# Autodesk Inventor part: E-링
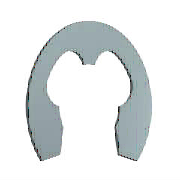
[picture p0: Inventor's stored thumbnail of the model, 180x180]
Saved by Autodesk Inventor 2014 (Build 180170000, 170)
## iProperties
IsCustomPart: 1
Created: 2012-02
Part Number: E-링
Material: 강철, 연강
Description: 일반용 테이퍼 및 줄어든 횡단면 리테이닝 링 - E-링 외부 시리즈 3CM1 리테이닝 링
Document SubType Name: Modeling
Standard: ANSI B27.7
Designer: mduedu
Standard Revision: 1999
Standards Organization: ANSI
Language: ko-KR
Size Designation: 6
Categories: <MemberInstance><Categories><Category DisplayName="샤프트 부품" InternalName="7f7aeb1f-a693-4053-b835-cee3144e0d98" Mnemonic="SHFT"><Category DisplayName="써클립" Inter
Density: 1 g/cm^3
Appearance: 파란색 - 벽 페인트 - 광택
Author: mduedu
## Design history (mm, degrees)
sketch "스케치1"
  geometry: L1 (-0.485, 0.024)-(0, 0.024) reference; L2 (-3.206, 0)-(3.486, 0) reference; L3 (-2.223, -3.946)-(2.223, -3.946); L4 (0, 1.949)-(0, -3.479) reference; L5 (-2.91, -2.006)-(-2.435, -2.006); L6 (-0.485, -0.066)-(-0.485, 0.405); L7 (0, 2.574)-(2.53, 2.574); L8 (-2.223, -3.946)-(-3.022, -6.291); L9 (0, -0.551)-(-1.278, -0.551); L10 (2.223, -3.946)-(3.022, -6.291); L11 (2.91, -2.006)-(2.435, -2.006); L12 (0.485, -0.066)-(0.485, 0.405); C1 r 3 at (0, -2.976); A1 r 2.425 centre (0, -2.976) between (-2.297, -2.199) and (-2.223, -3.946); A2 r 0.485 centre (0, -0.066) between (-0.485, -0.066) and (0.485, -0.066); A3 r 5.55 centre (0, -2.976) between (4.27, -6.521) and (-4.27, -6.521); A4 r 3.88 centre (0, -2.976) between (-0.97, 0.78) and (-3.424, -1.15); A5 r 0.388 centre (-0.873, 0.405) between (-0.485, 0.405) and (-0.97, 0.78); A6 r 0.582 centre (-2.91, -1.424) between (-3.424, -1.15) and (-2.91, -2.006); A7 r 0.145 centre (-2.435, -2.152) between (-2.297, -2.199) and (-2.435, -2.006); A8 r 0.727 centre (-3.711, -6.057) between (-4.27, -6.521) and (-3.022, -6.291); A9 r 0.727 centre (3.711, -6.057) between (3.022, -6.291) and (4.27, -6.521); A10 r 2.425 centre (0, -2.976) between (2.223, -3.946) and (2.297, -2.199); A11 r 0.145 centre (2.435, -2.152) between (2.435, -2.006) and (2.297, -2.199); A12 r 0.582 centre (2.91, -1.424) between (2.91, -2.006) and (3.424, -1.15); A13 r 3.88 centre (0, -2.976) between (3.424, -1.15) and (0.97, 0.78); A14 r 0.388 centre (0.873, 0.405) between (0.97, 0.78) and (0.485, 0.405); 1 further point
  constraints: 30 point on circle, 20 end point, 15 centre point, 13 symmetric about line, 12 tangent, 8 point on line, 4 parallel, 2 coincident, 2 horizontal, 1 concentric, 1 perpendicular, 1 vertical alignment, 9 other
  dimensions: "d0" = 6 diameter of C1 (= WD); "d3" = 0.97 distance from line of A1.centre L3 (= 0.2 x ND); "d4" = 0.485 radius of A2 (= 0.1 x ND); "d5" = 11.1 diameter of A3 (= SD2); "d8" = 3.88 radius of A4 (= 0.8 x ND); "d9" = 0.97 distance from line of A1.centre L5 (= 0.2 x ND); "d10" = 0.388 radius of A5 (= 0.08 x ND); "d11" = 0.582 radius of A6 (= 0.12 x ND); "d12" = 0.1455 radius of A7 (= 0.03 x ND); "d13" = 0.7275 radius of A8 (= 0.15 x ND); "d14" = 2.425 distance from line of A1.centre L9 (= 0.5 x ND); "d15" = 2.425 radius of A1 (= 0.5 x ND)
extrude "본체" new body sketch "스케치1" distance "d16" = 0.6 (= SD); taper "d17" = 0 deg
workaxis "Work Axis1"
workaxis "Work Axis2"
workplane "Work Plane1"
body "Solid1"
other parameters: "ND" = 4.85 [user parameter; used in 14 equation terms], "SD" = 0.6 [user parameter; used in 1 equation term], "WD" = 6 (= WDMIN) [user parameter; used in 1 equation term], "d1" = 7.76 (= 1.6 x ND), "d2" = 4.85 (= ND), "SD2" = 11.1 [user parameter; used in 1 equation term], "d6" = 4.85 (= ND), "d7" = 0.7275 (= 0.15 x ND), "d18" = 0, "d19" = 0, "d27" = 0, "d28" = 0, "WDMIN" = 6 [user parameter; used in 1 equation term], "SNB" = 0.7 [user parameter], "WDMAX" = 7 [user parameter], "BUBRMI" = 1.2 [user parameter]
